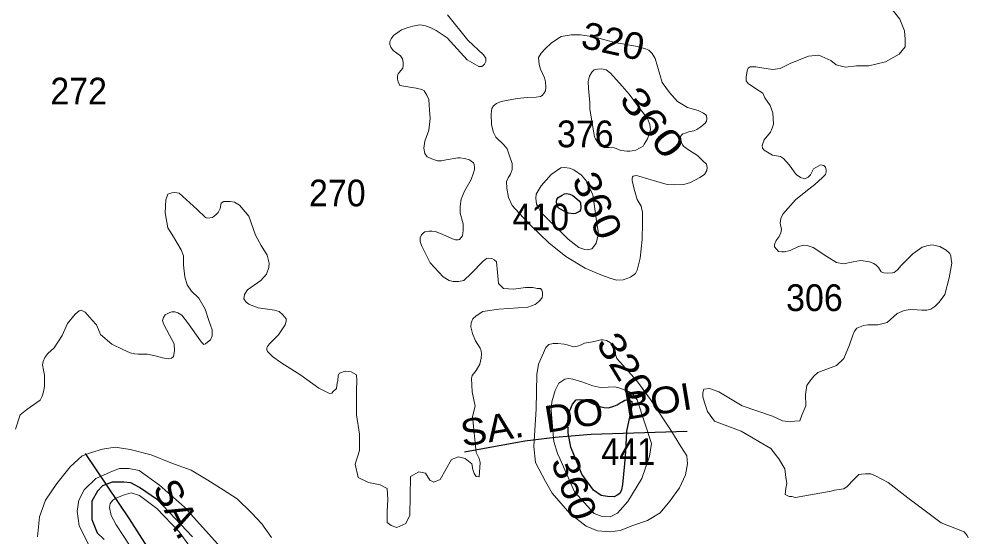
# Model space of a CAD drawing. Extents: x 445.4 to 500, y 8728.7 to 8784.
# Drawn here: x 479.66 to 485.34, y 8773.33 to 8776.43 of the extents above; entities that cross this region are included whole.
import ezdxf
from ezdxf.enums import TextEntityAlignment as Align

# ---------------------------------------------------------------- set-up
doc = ezdxf.new("R2010")
doc.units = 0
doc.header["$LTSCALE"] = 0.064
for name, color, linetype, lineweight in [('1', 7, 'Continuous', 25), ('2', 7, 'Continuous', 13), ('26', 7, 'Continuous', 25)]:
    doc.layers.add(name, color=color, linetype=linetype, lineweight=lineweight)
doc.layers.add('21', color=7, linetype='Continuous')
doc.layers.add('61', color=7, linetype='Continuous')

msp = doc.modelspace()

# ---------------------------------------------------------------- linework, layer by layer
at = {"layer": '1'}
for points in [[(482.915, 8775.3723), (482.9285, 8775.3808), (482.9403, 8775.3824), (482.9605, 8775.3791), (482.9791, 8775.3706), (483.0179, 8775.3386), (483.0246, 8775.3268), (483.0263, 8775.2965), (483.0246, 8775.2847), (483.0195, 8775.2746), (483.0077, 8775.2679), (482.9959, 8775.2628), (482.9824, 8775.2611), (482.9538, 8775.2645), (482.9234, 8775.278), (482.9048, 8775.2881), (482.8913, 8775.2965), (482.8863, 8775.3066), (482.8829, 8775.3184), (482.8812, 8775.3336), (482.8829, 8775.3471), (482.8913, 8775.3589)], [(483.2875, 8773.7635), (483.2763, 8773.6407), (483.2696, 8773.6094), (483.2606, 8773.5871), (483.245, 8773.5759), (483.2271, 8773.5669), (483.1868, 8773.5692), (483.1488, 8773.5736), (483.1018, 8773.6072), (483.0325, 8773.7032), (482.9676, 8773.8641), (482.9519, 8773.9501), (482.9497, 8774.0216), (482.9609, 8774.0842), (482.9765, 8774.1221), (482.9989, 8774.1467), (483.0235, 8774.1489), (483.0459, 8774.1467), (483.104, 8774.1221), (483.1398, 8774.1065), (483.1666, 8774.102), (483.1935, 8774.0998), (483.2248, 8774.1087), (483.2449, 8774.1177), (483.2628, 8774.1288), (483.274, 8774.1355), (483.2897, 8774.1445), (483.3098, 8774.1489), (483.3322, 8774.1378), (483.3344, 8774.1199), (483.3008, 8773.9591), (483.2941, 8773.8384)]]:
    msp.add_lwpolyline(points, close=True, dxfattribs=at)
msp.add_lwpolyline([(480.7016, 8773.3268), (480.4925, 8773.5493), (480.3846, 8773.6228), (480.334, 8773.6503), (480.2904, 8773.6549), (480.2214, 8773.6549), (480.164, 8773.6319), (480.1342, 8773.5998), (480.0997, 8773.5402), (480.0997, 8773.4966), (480.0997, 8773.43), (480.1319, 8773.352), (480.1732, 8773.3107)], dxfattribs=at)
at = {"layer": '2'}
for points in [[(484.4521, 8776.2101), (484.5233, 8776.1781), (484.5553, 8776.1532), (484.6122, 8776.139), (484.6763, 8776.1461), (484.751, 8776.1461), (484.8506, 8776.171), (484.9324, 8776.2172), (484.968, 8776.2599), (484.968, 8776.3061), (484.9644, 8776.3558), (484.936, 8776.4269), (484.8542, 8776.5299)], [(482.2295, 8776.4517), (482.3507, 8776.3006), (482.445, 8776.2133), (482.4575, 8776.1921), (482.4575, 8776.1721), (482.45, 8776.1571), (482.4425, 8776.1484), (482.4337, 8776.1434), (482.4162, 8776.1421), (482.3474, 8776.1834), (482.2274, 8776.3145), (482.1605, 8776.3577), (482.1255, 8776.3765), (482.098, 8776.3865), (482.0767, 8776.3902), (482.0617, 8776.3915), (482.0404, 8776.389), (482.0217, 8776.3852), (481.9929, 8776.3765), (481.9542, 8776.3627), (481.9054, 8776.329), (481.8916, 8776.309), (481.8829, 8776.2916), (481.8829, 8776.2753), (481.8891, 8776.2578), (481.9029, 8776.2378), (481.9467, 8776.2066), (481.9604, 8776.1882), (481.9642, 8776.167), (481.9642, 8776.1482), (481.9617, 8776.1333), (481.9492, 8776.1183), (481.9329, 8776.0983), (481.9292, 8776.0858), (481.9292, 8776.0671), (481.9329, 8776.0508), (481.9442, 8776.0283), (482.003, 8776.0183), (482.0405, 8776.0133), (482.0742, 8776.0046), (482.0892, 8775.9971), (482.1042, 8775.9709), (482.1168, 8775.9447), (482.1205, 8775.881), (482.1256, 8775.8314), (482.1168, 8775.7615), (482.093, 8775.6965), (482.0868, 8775.654), (482.093, 8775.6216), (482.1081, 8775.6016), (482.1343, 8775.5903), (482.1693, 8775.5779), (482.1931, 8775.5779)], [(482.6562, 8775.2672), (482.7225, 8775.1967), (482.8344, 8775.0882), (482.938, 8775.0061), (483.0521, 8774.9356), (483.1357, 8774.8987), (483.2063, 8774.8737), (483.2433, 8774.8629), (483.2802, 8774.8661), (483.3247, 8774.8824), (483.3541, 8774.9041), (483.3638, 8774.9236), (483.3823, 8774.9963), (483.3932, 8775.1081), (483.3957, 8775.2077), (483.3957, 8775.2695), (483.3881, 8775.3064), (483.3642, 8775.3465), (483.3458, 8775.4084), (483.3338, 8775.4611), (483.3349, 8775.4731), (483.3371, 8775.4818), (483.3404, 8775.4872), (483.3491, 8775.4893), (483.3599, 8775.4904), (483.3751, 8775.4861), (483.4827, 8775.4546), (483.5435, 8775.4362), (483.5891, 8775.434), (483.6434, 8775.4362), (483.6836, 8775.4481), (483.7401, 8775.4785), (483.7666, 8775.496), (483.7808, 8775.521), (483.7829, 8775.5373), (483.7818, 8775.5492), (483.7786, 8775.5579), (483.7601, 8775.5752), (483.7254, 8775.61), (483.6776, 8775.6403), (483.6428, 8775.6631), (483.6352, 8775.674), (483.6287, 8775.6881), (483.6254, 8775.7054), (483.6233, 8775.7239), (483.6287, 8775.7326), (483.6374, 8775.7391), (483.6515, 8775.7445), (483.6743, 8775.751), (483.7025, 8775.7575), (483.721, 8775.7651), (483.7449, 8775.7825), (483.771, 8775.8042), (483.7788, 8775.8157), (483.781, 8775.8298), (483.7788, 8775.8472), (483.7744, 8775.8537), (483.7614, 8775.8645), (483.7299, 8775.8786), (483.6647, 8775.8971), (483.6061, 8775.934), (483.5572, 8775.9882), (483.5146, 8776.0474), (483.4711, 8776.1906), (483.4548, 8776.2199), (483.4342, 8776.2405), (483.4146, 8776.2492), (483.3668, 8776.2622), (483.2295, 8776.2867), (483.1046, 8776.3204), (483.0242, 8776.3334), (482.9692, 8776.3322), (482.9094, 8776.3224), (482.8519, 8776.2855), (482.8127, 8776.2487), (482.7889, 8776.2226), (482.7736, 8776.1977), (482.778, 8776.1554), (482.7846, 8776.1263), (482.8085, 8776.0753), (482.8161, 8776.0503), (482.8183, 8776.0189), (482.8161, 8775.9972), (482.8063, 8775.982), (482.7954, 8775.969), (482.7846, 8775.9625), (482.7596, 8775.9603), (482.7064, 8775.9581), (482.6466, 8775.9505), (482.5815, 8775.9397), (482.5499, 8775.9343), (482.5212, 8775.9218), (482.5049, 8775.9077), (482.494, 8775.8914), (482.4908, 8775.86), (482.4929, 8775.7927), (482.5038, 8775.7471), (482.519, 8775.72), (482.5668, 8775.6734), (482.5855, 8775.6498), (482.6007, 8775.6075)], [(484.9628, 8774.6814), (484.9986, 8774.6882), (485.0395, 8774.6865), (485.0684, 8774.6848), (485.099, 8774.6848), (485.1212, 8774.6899), (485.1467, 8774.7069), (485.1722, 8774.7324), (485.2063, 8774.7783), (485.2318, 8774.8769), (485.2472, 8774.9662), (485.2438, 8774.9866), (485.2421, 8775.0087), (485.2353, 8775.024), (485.2132, 8775.0427), (485.1757, 8775.0648), (485.1297, 8775.075), (485.1059, 8775.0716), (485.0702, 8775.0614), (485.014, 8775.0206), (484.9442, 8774.9509), (484.922, 8774.9254), (484.9033, 8774.9101), (484.8931, 8774.9067), (484.8625, 8774.905), (484.8403, 8774.9067), (484.825, 8774.9135), (484.825, 8774.9135), (484.8097, 8774.939), (484.7944, 8774.9543), (484.7807, 8774.9628), (484.7552, 8774.973), (484.7178, 8774.9798), (484.7007, 8774.9815), (484.6565, 8774.973), (484.5986, 8774.9611), (484.5583, 8774.9699), (484.5004, 8775.0056), (484.417, 8775.06), (484.3813, 8775.0719), (484.3574, 8775.0736), (484.3268, 8775.0634), (484.2791, 8775.0413), (484.2468, 8775.0328), (484.2297, 8775.0328), (484.211, 8775.0362), (484.211, 8775.0362), (484.1867, 8775.0623), (484.1867, 8775.0782), (484.1963, 8775.1004), (484.215, 8775.126), (484.2251, 8775.1475), (484.2279, 8775.1662), (484.2207, 8775.2049), (484.2236, 8775.2322), (484.2366, 8775.2595), (484.3113, 8775.3441), (484.3732, 8775.3937), (484.4278, 8775.4367), (484.4738, 8775.4784), (484.491, 8775.4956), (484.4953, 8775.5128), (484.4953, 8775.5228), (484.4924, 8775.5401), (484.4824, 8775.5501), (484.4623, 8775.5544), (484.4206, 8775.53), (484.4019, 8775.4941), (484.3876, 8775.4798), (484.3675, 8775.4712), (484.3416, 8775.4784), (484.3157, 8775.4956), (484.2741, 8775.5544), (484.2396, 8775.5917), (484.2224, 8775.6032), (484.1749, 8775.6118), (484.1244, 8775.6428), (484.1143, 8775.6542), (484.1114, 8775.67), (484.1244, 8775.703), (484.1617, 8775.749), (484.1732, 8775.7733), (484.1794, 8775.7967), (484.1757, 8775.866), (484.1611, 8775.9097), (484.1283, 8775.9553), (484.1154, 8775.9833), (484.0661, 8776.0143), (484.0278, 8776.0417), (484.0168, 8776.0581), (484.0168, 8776.0799), (484.0223, 8776.1164), (484.0278, 8776.1328), (484.0405, 8776.1401), (484.0752, 8776.1419), (484.1099, 8776.1346), (484.1737, 8776.1255), (484.2193, 8776.131), (484.2832, 8776.1619), (484.389, 8776.2057), (484.4521, 8776.2101)], [(482.6007, 8775.6075), (482.616, 8775.5619), (482.616, 8775.5272), (482.6051, 8775.4979), (482.591, 8775.4762), (482.5823, 8775.4535), (482.5834, 8775.4155), (482.5932, 8775.3594), (482.616, 8775.3105), (482.6562, 8775.2672)], [(482.1931, 8775.5779), (482.2206, 8775.5841), (482.2898, 8775.5958), (482.3048, 8775.5971), (482.331, 8775.5921), (482.3598, 8775.5833), (482.371, 8775.5758), (482.3848, 8775.5658), (482.3885, 8775.5571), (482.391, 8775.5371), (482.391, 8775.5271), (482.3848, 8775.5059), (482.3698, 8775.4659), (482.331, 8775.396), (482.311, 8775.3485), (482.3048, 8775.3048), (482.3048, 8775.264), (482.3223, 8775.2003), (482.3236, 8775.1604), (482.3186, 8775.1291), (482.3086, 8775.1167), (482.2998, 8775.1079), (482.2935, 8775.1054), (482.2773, 8775.1042), (482.2585, 8775.1104), (482.201, 8775.1379), (482.156, 8775.1554), (482.136, 8775.1579), (482.1185, 8775.1566), (482.0922, 8775.1529), (482.0847, 8775.1466), (482.0722, 8775.1354), (482.066, 8775.1179), (482.066, 8775.0954), (482.0735, 8775.0704), (482.126, 8774.968), (482.2023, 8774.8843), (482.2386, 8774.861), (482.2636, 8774.856), (482.2948, 8774.856), (482.3261, 8774.8622), (482.3699, 8774.9035), (482.4426, 8774.9779), (482.4613, 8774.9929), (482.4738, 8774.9954), (482.4938, 8774.9941), (482.5076, 8774.9854), (482.5226, 8774.9729), (482.5291, 8774.9104), (482.5341, 8774.8444), (482.5646, 8774.814), (482.623, 8774.8089), (482.6966, 8774.8191), (482.7398, 8774.8191), (482.7651, 8774.814), (482.7862, 8774.8144), (482.7862, 8774.8144), (482.7937, 8774.8037), (482.7969, 8774.7919), (482.798, 8774.7726), (482.7948, 8774.7608), (482.7862, 8774.7457), (482.7744, 8774.7339), (482.754, 8774.7189), (482.7099, 8774.7018), (482.537, 8774.691), (482.4404, 8774.676), (482.3996, 8774.6503), (482.3802, 8774.632), (482.3695, 8774.6074), (482.3684, 8774.5848), (482.3781, 8774.5441), (482.3974, 8774.5005), (482.4242, 8774.4576), (482.4307, 8774.4404), (482.4328, 8774.42), (482.4307, 8774.3975), (482.4232, 8774.361), (482.3995, 8774.3235), (482.377, 8774.2934), (482.3727, 8774.2752), (482.3769, 8774.1949), (482.395, 8774.1093), (482.3788, 8774.0469), (482.4009, 8773.8325), (482.4188, 8773.7957), (482.424, 8773.7715), (482.4174, 8773.6861), (482.3996, 8773.6891), (482.3885, 8773.7057), (482.3812, 8773.7299), (482.3748, 8773.7635), (482.3352, 8773.7952), (482.2946, 8773.8051), (482.2529, 8773.7902), (482.1856, 8773.6713), (482.1479, 8773.6544), (482.1222, 8773.6673), (482.0974, 8773.7089), (482.0568, 8773.7169), (482.0082, 8773.6891)], [(482.0082, 8773.6891), (482.0042, 8773.4574), (481.9786, 8773.4061), (481.9248, 8773.383), (481.8915, 8773.3958), (481.8685, 8773.4138), (481.8685, 8773.4804), (481.871, 8773.5496), (481.8685, 8773.6163), (481.8249, 8773.6393), (481.7558, 8773.6521), (481.6943, 8773.6829), (481.6763, 8773.7624), (481.702, 8773.8444), (481.702, 8773.9418), (481.684, 8774.0571), (481.6835, 8774.2081), (481.6866, 8774.2611), (481.6841, 8774.2964), (481.6523, 8774.3146), (481.6159, 8774.3187), (481.5816, 8774.3075), (481.5735, 8774.2939), (481.5725, 8774.2616), (481.5675, 8774.2485), (481.5649, 8774.2147), (481.5448, 8774.1965), (481.5357, 8774.1874), (481.5246, 8774.1853), (481.5148, 8774.1894), (481.4593, 8774.2175), (481.35, 8774.2955), (481.2307, 8774.3711), (481.1819, 8774.407), (481.1589, 8774.4291), (481.1515, 8774.4374), (481.1482, 8774.4464), (481.1482, 8774.4579), (481.1523, 8774.4669), (481.1638, 8774.4817), (481.2181, 8774.5367), (481.2568, 8774.5966), (481.2634, 8774.6181), (481.2634, 8774.6331), (481.2435, 8774.6563), (481.2203, 8774.6762), (481.1937, 8774.6845), (481.0957, 8774.6978), (481.0641, 8774.7094), (481.0392, 8774.721), (481.0243, 8774.7326), (481.0093, 8774.7525), (481.0127, 8774.7786), (481.031, 8774.8051), (481.1107, 8774.8615), (481.1456, 8774.8997), (481.1589, 8774.9395), (481.1622, 8774.9661), (481.1489, 8775.0142), (481.114, 8775.0706), (481.0791, 8775.1336), (481.0393, 8775.2473), (480.9845, 8775.3137), (480.9546, 8775.3303), (480.928, 8775.3353), (480.8898, 8775.3353), (480.8748, 8775.3253), (480.8682, 8775.2921), (480.8566, 8775.2689), (480.8416, 8775.254), (480.8217, 8775.239), (480.8217, 8775.239), (480.7918, 8775.2357), (480.7802, 8775.239), (480.7303, 8775.2872), (480.6644, 8775.3471), (480.6229, 8775.3836), (480.5946, 8775.3885), (480.5797, 8775.3869), (480.5548, 8775.3786), (480.5431, 8775.3437), (480.5398, 8775.2674), (480.5548, 8775.1778), (480.588, 8775.1231), (480.6348, 8775.0458), (480.6481, 8775.0093), (480.6481, 8774.9545), (480.6564, 8774.8832), (480.6713, 8774.8367), (480.6963, 8774.7986), (480.7411, 8774.7555), (480.7778, 8774.6895), (480.8011, 8774.6215), (480.821, 8774.5667), (480.8194, 8774.5302), (480.8094, 8774.507), (480.7928, 8774.492), (480.7803, 8774.4822), (480.7698, 8774.4791), (480.757, 8774.4919), (480.6718, 8774.6109)], [(480.6718, 8774.6109), (480.6386, 8774.6546), (480.6142, 8774.6676), (480.5962, 8774.6737), (480.5796, 8774.6737), (480.566, 8774.6706), (480.5396, 8774.6563), (480.5298, 8774.6405), (480.5238, 8774.6224), (480.5283, 8774.6014), (480.5652, 8774.5336), (480.5917, 8774.4821), (480.5943, 8774.4409), (480.5879, 8774.4074), (480.5776, 8774.3971), (480.577, 8774.3969), (480.5582, 8774.3936), (480.5225, 8774.3988), (480.4783, 8774.4104), (480.4326, 8774.4198), (480.3769, 8774.4214), (480.3559, 8774.4224), (480.329, 8774.4287), (480.2852, 8774.4479), (480.2194, 8774.481), (480.1516, 8774.5392), (480.1278, 8774.5971), (480.1015, 8774.6245), (480.0606, 8774.6718), (480.0369, 8774.6847), (480.0239, 8774.6804), (480.0002, 8774.6611), (479.955, 8774.6051), (479.9227, 8774.532), (479.8753, 8774.4588), (479.8365, 8774.4244), (479.8193, 8774.4007), (479.8085, 8774.3771), (479.8042, 8774.3577), (479.8107, 8774.3254), (479.8171, 8774.2953), (479.8167, 8774.2274), (479.8103, 8774.1951), (479.8017, 8774.1693), (479.7909, 8774.1456), (479.7112, 8774.0897), (479.6702, 8774.0574), (479.6422, 8773.9713)], [(485.3446, 8773.3215), (485.3404, 8773.3341), (485.3208, 8773.3565), (485.1845, 8773.4112), (484.9837, 8773.5599), (484.8663, 8773.6518), (484.7904, 8773.6925), (484.7637, 8773.7051), (484.7314, 8773.7051), (484.7062, 8773.7023), (484.6907, 8773.7009), (484.6598, 8773.6686), (484.6219, 8773.6294), (484.6008, 8773.6153), (484.5461, 8773.6069), (484.525, 8773.6013), (484.423, 8773.5832), (484.3129, 8773.5624), (484.2891, 8773.5684), (484.2742, 8773.5684), (484.2504, 8773.5803), (484.2533, 8773.6159), (484.2593, 8773.6487), (484.2533, 8773.6814), (484.2474, 8773.7349), (484.2117, 8773.7944), (484.164, 8773.8568), (483.9869, 8773.9593), (483.8262, 8774.0188), (483.7845, 8774.0783), (483.7666, 8774.1318), (483.7577, 8774.1645), (483.7577, 8774.1883), (483.7577, 8774.1883), (483.7636, 8774.2121), (483.7636, 8774.2121), (483.7964, 8774.2151), (483.853, 8774.1943), (483.9929, 8774.111), (484.1745, 8774.0486), (484.2341, 8774.0218), (484.2817, 8774.0159), (484.3085, 8774.0188), (484.3383, 8774.0218), (484.3502, 8774.0545), (484.374, 8774.111), (484.371, 8774.1794), (484.3799, 8774.2329), (484.3978, 8774.2597), (484.4216, 8774.2895), (484.4454, 8774.3103), (484.5575, 8774.3523), (484.6022, 8774.394), (484.6349, 8774.4772), (484.6558, 8774.5337), (484.6647, 8774.5575), (484.6796, 8774.5754), (484.7183, 8774.5932), (484.7451, 8774.5962), (484.8046, 8774.5962), (484.8612, 8774.6111), (484.9203, 8774.6644), (484.9628, 8774.6814)], [(481.1759, 8773.3232), (481.1173, 8773.4057), (481.0553, 8773.471), (480.9692, 8773.5536), (480.8865, 8773.6086), (480.7935, 8773.667), (480.6936, 8773.7255), (480.573, 8773.7702), (480.4559, 8773.8183), (480.3284, 8773.8493), (480.2388, 8773.863), (480.163, 8773.8527), (480.0975, 8773.8321)], [(480.0975, 8773.8321), (480.0424, 8773.8115), (479.9701, 8773.7461), (479.8908, 8773.6464), (479.8219, 8773.5467), (479.7875, 8773.447), (479.7737, 8773.3266)], [(480.9433, 8773.1839), (480.6537, 8773.5056), (480.504, 8773.6356), (480.3836, 8773.7234), (480.3217, 8773.7364), (480.2664, 8773.7364), (480.2241, 8773.7202)], [(480.2241, 8773.7202), (480.1243, 8773.6754), (480.0539, 8773.6083), (480.0211, 8773.5474), (480.0117, 8773.4803), (480.0242, 8773.3928), (480.0852, 8773.2711)], [(480.3297, 8773.2714), (480.2459, 8773.3992), (480.2159, 8773.4542), (480.2059, 8773.5025), (480.2092, 8773.5259), (480.2259, 8773.5459), (480.2443, 8773.5592), (480.2693, 8773.5692), (480.2926, 8773.5792), (480.321, 8773.5875), (480.3344, 8773.5908), (480.3861, 8773.5742), (480.4895, 8773.4959), (480.623, 8773.3576), (480.7319, 8773.2063)]]:
    msp.add_lwpolyline(points, dxfattribs=at)
for points in [[(483.0806, 8775.9259), (483.073, 8776.0118), (483.0711, 8776.0525), (483.0797, 8776.085), (483.0931, 8776.1089), (483.1075, 8776.1232), (483.1266, 8776.127), (483.1505, 8776.1289), (483.1782, 8776.1223), (483.2041, 8776.1022), (483.2748, 8776.0258), (483.3169, 8775.9781), (483.3726, 8775.901), (483.4261, 8775.8322), (483.4395, 8775.7959), (483.4433, 8775.7663), (483.4366, 8775.7377), (483.4261, 8775.71), (483.406, 8775.6779), (483.3993, 8775.6665), (483.3783, 8775.6531), (483.3563, 8775.6426), (483.3343, 8775.6378), (483.3199, 8775.6369), (483.3018, 8775.6359), (483.2855, 8775.6378), (483.2673, 8775.6397), (483.2377, 8775.6522), (483.2262, 8775.656), (483.1966, 8775.6579), (483.1784, 8775.6579), (483.1669, 8775.6588), (483.1516, 8775.6636), (483.1421, 8775.6703), (483.1325, 8775.6818), (483.1153, 8775.7104), (483.1096, 8775.7209), (483.1057, 8775.7448), (483.0818, 8775.8866)], [(482.7893, 8775.4289), (482.8492, 8775.497), (482.9065, 8775.5357), (482.9285, 8775.5391), (482.9588, 8775.5341), (482.9858, 8775.5239), (483.0313, 8775.4919), (483.0617, 8775.4566), (483.0988, 8775.374), (483.1089, 8775.3049), (483.1207, 8775.219), (483.1309, 8775.155), (483.1292, 8775.1264), (483.1191, 8775.0843), (483.1039, 8775.0657), (483.0921, 8775.0506), (483.0668, 8775.0455), (483.0499, 8775.0472), (483.0145, 8775.059), (482.9521, 8775.1095), (482.7885, 8775.2713), (482.775, 8775.2948), (482.7615, 8775.3184), (482.7581, 8775.3538), (482.7598, 8775.3791)], [(483.4442, 8774.15), (483.5648, 8773.9656), (483.6251, 8773.8677), (483.6609, 8773.8112), (483.6647, 8773.7642), (483.6534, 8773.6987), (483.6176, 8773.6196), (483.5592, 8773.5406), (483.5027, 8773.4709), (483.4254, 8773.4239), (483.3387, 8773.3957), (483.2615, 8773.3653), (483.203, 8773.3561), (483.1276, 8773.3637), (483.0579, 8773.3919), (482.9618, 8773.4672), (482.8562, 8773.5876), (482.8158, 8773.6583), (482.7555, 8773.7713), (482.7461, 8773.8672), (482.7593, 8774.0931), (482.7632, 8774.2993), (482.7726, 8774.3614), (482.8179, 8774.4611), (482.8348, 8774.4781), (482.8612, 8774.4837), (482.8895, 8774.4837), (482.9272, 8774.48), (482.946, 8774.4762), (482.9837, 8774.4649), (483.0063, 8774.4687), (483.0289, 8774.4762), (483.0497, 8774.4875), (483.0968, 8774.495), (483.1232, 8774.5007), (483.1458, 8774.5063), (483.159, 8774.5063), (483.1797, 8774.5025), (483.2042, 8774.4894), (483.2155, 8774.4743), (483.2419, 8774.3953), (483.3625, 8774.2616)], [(482.8877, 8773.8259), (482.8651, 8773.8972), (482.8614, 8773.9415), (482.8495, 8774.0854), (482.8525, 8774.1346), (482.8728, 8774.2037), (482.8961, 8774.2465), (482.9307, 8774.272), (482.954, 8774.275), (482.9796, 8774.2713), (483.0322, 8774.2555), (483.0983, 8774.2315), (483.1517, 8774.2195), (483.1897, 8774.2223), (483.2296, 8774.2246), (483.2544, 8774.2201), (483.3133, 8774.1968), (483.3378, 8774.1817), (483.3636, 8774.1472), (483.4083, 8774.0132), (483.4508, 8773.8858), (483.4374, 8773.8099), (483.3926, 8773.6764), (483.3076, 8773.5379), (483.2472, 8773.4687), (483.2025, 8773.4463), (483.1555, 8773.4485), (483.1063, 8773.4664), (482.99, 8773.596), (482.9005, 8773.797)]]:
    msp.add_lwpolyline(points, close=True, dxfattribs=at)
at = {"layer": '26'}
for points in [[(482.3305, 8773.8352), (482.692, 8773.9025), (482.8728, 8773.9238), (483.089, 8773.9415), (483.6632, 8773.9592)], [(480.0596, 8773.826), (480.324, 8773.4351), (480.8529, 8772.6074), (481.1288, 8772.1361), (481.3357, 8771.7452), (481.4622, 8771.3543), (481.6001, 8770.906), (481.8645, 8769.5839)]]:
    msp.add_lwpolyline(points, dxfattribs=at)

# ---------------------------------------------------------------- texts
at = {"layer": '21'}
for s, width, p in [('272', 0.95, (479.8514, 8775.9158)), ('270', 0.95, (481.3997, 8775.3056)), ('306', 0.95, (484.2556, 8774.6788)), ('441', 0.9, (483.1502, 8773.7571))]:
    msp.add_text(s, height=0.16, dxfattribs=dict(at, width=width)).set_placement(p)
at = {"layer": '21', "width": 0.95}
for s, p in [('376', (483.2231, 8775.6595)), ('410', (482.9569, 8775.1618))]:
    msp.add_text(s, height=0.16, dxfattribs=at).set_placement(p, align=Align.RIGHT)
at = {"layer": '26'}
for s, rotation, width, p in [('SA.  DO  BOI', 9.324, 1.1, (483.0112, 8773.98)), ('SA.    PEDRA    ALTA    S.    ANTONIO', 297.079, 1.05, (481.3562, 8771.8694))]:
    msp.add_text(s, height=0.16, rotation=rotation, dxfattribs=dict(at, width=width)).set_placement(p, align=Align.CENTER)
at = {"layer": '61'}
for s, rotation, width, p in [('320', 347.46, 1.05, (483.2028, 8776.2171)), ('360', 307.387, 1.3, (483.3915, 8775.7602)), ('360', 293.542, 1.15, (483.0533, 8775.2797)), ('320', 301.407, 1.2, (483.2258, 8774.3045)), ('360', 289.643, 1.1, (482.9123, 8773.596))]:
    msp.add_text(s, height=0.16, rotation=rotation, dxfattribs=dict(at, width=width)).set_placement(p, align=Align.CENTER)

doc.saveas('drawing.dxf')
